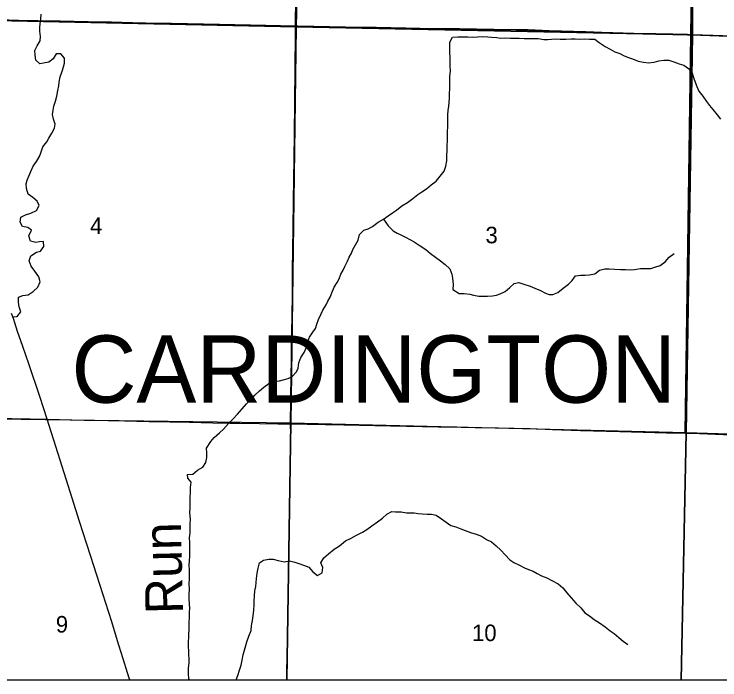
# Model space of a CAD drawing. Extents: x 0 to 34, y 0 to 22.
# Drawn here: x 5.278 to 7.066, y 14 to 15.686 of the extents above; entities that cross this region are included whole.
import ezdxf

# ---------------------------------------------------------------- set-up
doc = ezdxf.new("R2010")
doc.units = 0
for name, color, linetype in [('Default', 7, 'Continuous'), ('GM_X_City_Street', 7, 'Continuous'), ('GM_X_Corporation_Text', 7, 'Continuous'), ('GM_X_Interchange_Ramps', 7, 'Continuous'), ('GM_X_Major_River_Text', 7, 'Continuous'), ('GM_X_Minor_River', 7, 'Continuous'), ('GM_X_Section', 7, 'Continuous'), ('GM_X_Unincorporated_Location', 7, 'Continuous'), ('SH_Cut_Line', 7, 'Continuous'), ('SH_Text', 7, 'Continuous')]:
    doc.layers.add(name, color=color, linetype=linetype)

msp = doc.modelspace()

# ---------------------------------------------------------------- linework, layer by layer
at = {"layer": 'Default'}
for points in [[(7.0145, 17.1525), (7.0025, 16.32), (6.9926, 15.6339), (6.978, 14.6253), (6.9941, 14.625), (7.0745, 14.6221)], [(5.2396, 15.6714), (5.2884, 15.6704), (5.3381, 15.6694), (5.394, 15.6683), (5.4654, 15.6668), (5.5244, 15.6654), (5.5772, 15.6642), (5.6114, 15.6635), (5.6766, 15.6622), (5.7977, 15.6597), (5.9158, 15.6575), (5.9904, 15.6556), (5.9965, 15.6555), (6.1176, 15.6533), (6.1953, 15.6519), (6.2698, 15.6504), (6.3413, 15.6493), (6.4065, 15.6489), (6.4935, 15.6475), (6.5494, 15.6467), (6.5805, 15.646), (6.6332, 15.6442), (6.7264, 15.6417), (6.7668, 15.64), (6.7947, 15.6388), (6.8475, 15.6374), (6.9034, 15.6361), (6.9468, 15.6351), (6.9841, 15.6342), (6.9926, 15.6339), (7.0025, 16.32)], [(7.0745, 14.6221), (6.9941, 14.625), (6.978, 14.6253), (6.9926, 15.6339), (6.9841, 15.6342), (6.9468, 15.6351), (6.9034, 15.6361), (6.8475, 15.6374), (6.7947, 15.6388), (6.7668, 15.64), (6.7264, 15.6417), (6.6332, 15.6442), (6.5805, 15.646), (6.5494, 15.6467), (6.4935, 15.6475), (6.4065, 15.6489), (6.3413, 15.6493), (6.2698, 15.6504), (6.1953, 15.6519), (6.1176, 15.6533), (5.9965, 15.6555), (5.9904, 15.6556), (5.9158, 15.6575), (5.7977, 15.6597), (5.6766, 15.6622), (5.6114, 15.6635), (5.5772, 15.6642), (5.5244, 15.6654), (5.4654, 15.6668), (5.394, 15.6683), (5.3381, 15.6694), (5.2884, 15.6704), (5.2396, 15.6714)], [(2.9377, 14), (7.9275, 14)]]:
    msp.add_lwpolyline(points, dxfattribs=at)
for points in [[(4.9774, 14), (5.9688, 14), (5.9788, 14.6503), (4.9836, 14.6638)], [(5.9688, 14), (6.9678, 14), (6.9808, 14.6254), (5.9788, 14.6503)], [(6.9678, 14), (7.9307, 14), (7.9448, 14.3373), (7.9551, 14.5952), (6.9808, 14.6254)]]:
    msp.add_lwpolyline(points, close=True, dxfattribs=at)
at = {"layer": 'GM_X_City_Street'}
for points in [[(5.9907, 15.6551), (5.9907, 15.6636), (5.9909, 15.6791), (5.9921, 15.7319), (5.9933, 15.7816), (5.9942, 15.822), (5.9965, 15.9277), (5.9973, 15.9649), (5.9979, 15.9991), (5.9988, 16.0551), (6.0006, 16.1545), (6.0016, 16.198), (6.0023, 16.2353), (6.0032, 16.2881), (6.0042, 16.3347), (6.0058, 16.4159)], [(5.2398, 15.6709), (5.2886, 15.6698), (5.3383, 15.6688), (5.3942, 15.6678), (5.4656, 15.6662), (5.5246, 15.6649), (5.5774, 15.6637), (5.6116, 15.663), (5.6768, 15.6617), (5.7979, 15.6591), (5.916, 15.6569), (5.9907, 15.6551)], [(5.9907, 15.6551), (5.9967, 15.6549), (6.1179, 15.6527), (6.1955, 15.6513), (6.2701, 15.6499), (6.3415, 15.6488), (6.3796, 15.6485)], [(6.3796, 15.6485), (6.4067, 15.6484), (6.4937, 15.647), (6.5496, 15.6462), (6.5807, 15.6455), (6.6335, 15.6437), (6.7266, 15.6411), (6.7508, 15.6401)], [(6.7508, 15.6401), (6.767, 15.6395), (6.7949, 15.6382), (6.8477, 15.6369), (6.9036, 15.6356), (6.9471, 15.6345), (6.9843, 15.6336), (6.9928, 15.6334)], [(6.9928, 15.6334), (7.0402, 15.6319), (7.0868, 15.6305), (7.1613, 15.6285), (7.2265, 15.6267), (7.2855, 15.625), (7.3632, 15.6225), (7.4315, 15.6206), (7.4563, 15.6198), (7.4905, 15.6191), (7.4938, 15.619)]]:
    msp.add_lwpolyline(points, dxfattribs=at)
at = {"layer": 'GM_X_Interchange_Ramps'}
for points in [[(5.9783, 14.6481), (5.9783, 14.6505), (5.9788, 14.7096), (5.9797, 14.7749), (5.9801, 14.8059), (5.9809, 14.8588), (5.9819, 14.9147), (5.9829, 14.9831), (5.9834, 15.0422), (5.984, 15.0857), (5.9848, 15.1478), (5.9855, 15.21), (5.9868, 15.2722), (5.9873, 15.3157), (5.988, 15.3872), (5.9889, 15.4556), (5.99, 15.555), (5.9906, 15.6297), (5.9906, 15.6441), (5.9907, 15.6551)], [(5.3613, 14.6602), (5.3425, 14.7179), (5.3148, 14.8004), (5.2997, 14.8445), (5.2865, 14.8827), (5.2759, 14.9151), (5.2714, 14.9283)], [(4.9831, 14.6676), (4.9983, 14.6676), (5.0667, 14.6663), (5.1071, 14.6656), (5.1661, 14.6644), (5.2251, 14.6631), (5.3183, 14.6613), (5.3556, 14.6604), (5.3613, 14.6602)], [(5.5705, 14), (5.5691, 14.0042), (5.5498, 14.0665), (5.5424, 14.0902), (5.525, 14.1466), (5.4871, 14.265), (5.4711, 14.3154), (5.4434, 14.4011), (5.4246, 14.4603), (5.3993, 14.5403), (5.3835, 14.5907), (5.3666, 14.6441), (5.3613, 14.6602)], [(5.3613, 14.6602), (5.455, 14.658), (5.516, 14.6568), (5.5575, 14.6561), (5.6196, 14.6544), (5.6724, 14.6534), (5.7221, 14.6528), (5.7811, 14.6514), (5.8246, 14.6502), (5.8494, 14.6498), (5.8991, 14.6493), (5.9457, 14.6485), (5.9783, 14.6481)], [(5.9686, 14), (5.969, 14.0258), (5.9701, 14.0817), (5.9718, 14.1719), (5.9732, 14.2527), (5.9738, 14.29), (5.9742, 14.3211), (5.9747, 14.3583), (5.976, 14.4392), (5.9771, 14.5169), (5.9777, 14.5666), (5.9784, 14.6226), (5.9783, 14.6481)], [(5.9783, 14.6481), (5.9799, 14.6481), (6.0203, 14.6476), (6.0669, 14.6468), (6.1135, 14.6459), (6.2315, 14.6437), (6.3527, 14.6413), (6.3993, 14.6405), (6.4104, 14.6403)], [(6.4104, 14.6403), (6.4459, 14.6396), (6.5049, 14.6385), (6.5856, 14.6366), (6.6415, 14.6345), (6.7129, 14.632), (6.7782, 14.6303), (6.8123, 14.6292), (6.9304, 14.6261), (6.9782, 14.6247)], [(6.9782, 14.6247), (6.9944, 14.6245), (7.0747, 14.6216), (7.1304, 14.62), (7.2045, 14.6182), (7.2347, 14.6173)]]:
    msp.add_lwpolyline(points, dxfattribs=at)
at = {"layer": 'GM_X_Section'}
for points in [[(5.3517, 15.1102), (5.3419, 15.1095), (5.3324, 15.1079), (5.3195, 15.1109), (5.3153, 15.1249), (5.3216, 15.1386), (5.3121, 15.1461), (5.2985, 15.1484), (5.2931, 15.1594), (5.295, 15.1723), (5.3067, 15.178), (5.3204, 15.1822), (5.334, 15.1887), (5.3411, 15.2016), (5.3362, 15.2126), (5.3248, 15.2217), (5.313, 15.23), (5.3091, 15.2444), (5.3083, 15.2565), (5.311, 15.266), (5.3151, 15.2755), (5.32, 15.288), (5.326, 15.3013), (5.3347, 15.3131), (5.3422, 15.3253), (5.3456, 15.3347), (5.3501, 15.3503), (5.3603, 15.3625), (5.366, 15.372), (5.3735, 15.3849), (5.3799, 15.3974), (5.3818, 15.4073), (5.3775, 15.4198), (5.3745, 15.4323), (5.3763, 15.4426), (5.3786, 15.4528), (5.3827, 15.4657), (5.3861, 15.4786), (5.3883, 15.4927), (5.3909, 15.5044), (5.392, 15.5139), (5.3942, 15.5272), (5.3995, 15.542), (5.4032, 15.5526), (5.4055, 15.5621), (5.4054, 15.5746), (5.3963, 15.5856), (5.3841, 15.5859), (5.3762, 15.5726), (5.3653, 15.5643), (5.3524, 15.5616), (5.3425, 15.5604), (5.333, 15.5695), (5.3307, 15.582), (5.3303, 15.5937), (5.3359, 15.6059), (5.3434, 15.6184), (5.3442, 15.6298), (5.3426, 15.6427), (5.3426, 15.6522), (5.3437, 15.6617), (5.3455, 15.6738), (5.3466, 15.6863)], [(6.0444, 14.9005), (6.0492, 14.9131), (6.0553, 14.9271), (6.0598, 14.9366), (6.0681, 14.9499), (6.0722, 14.9594), (6.0783, 14.9693), (6.0831, 14.9799), (6.0888, 14.9944), (6.0963, 15.0061), (6.1012, 15.016), (6.1054, 15.0274), (6.111, 15.0377), (6.1159, 15.0472), (6.1223, 15.0608), (6.1268, 15.0703), (6.1325, 15.0806), (6.1359, 15.0901), (6.1423, 15.1015), (6.149, 15.114), (6.1524, 15.1281), (6.1638, 15.1391), (6.1744, 15.1422), (6.1861, 15.1483), (6.1997, 15.1589), (6.2137, 15.1666), (6.2258, 15.1753), (6.2364, 15.1826), (6.2463, 15.1894), (6.2603, 15.2009), (6.2743, 15.2093), (6.2879, 15.2192), (6.3007, 15.2294), (6.3106, 15.2359), (6.3223, 15.2435), (6.3348, 15.2535), (6.3469, 15.263), (6.3575, 15.2755), (6.3677, 15.2885), (6.3718, 15.3014), (6.3737, 15.3143), (6.374, 15.3279), (6.3747, 15.3408), (6.3746, 15.3541), (6.3757, 15.364), (6.3757, 15.3768), (6.376, 15.3901), (6.3768, 15.4), (6.3763, 15.4095), (6.3763, 15.422), (6.377, 15.4315), (6.3777, 15.4417), (6.3792, 15.4531), (6.3803, 15.4626), (6.381, 15.4732), (6.381, 15.4846), (6.3813, 15.4975), (6.3817, 15.5073), (6.3813, 15.518), (6.382, 15.5282), (6.3831, 15.5422), (6.3826, 15.554), (6.3822, 15.5665), (6.3826, 15.576), (6.3821, 15.5893), (6.3813, 15.6029), (6.3817, 15.6154), (6.3885, 15.6276), (6.4021, 15.6284), (6.4135, 15.6288), (6.4275, 15.6285), (6.4385, 15.6281), (6.4514, 15.6289), (6.4651, 15.6297), (6.4776, 15.6286), (6.4871, 15.6279), (6.5007, 15.6272), (6.5102, 15.6257), (6.5231, 15.6261), (6.5353, 15.625), (6.5573, 15.6251), (6.5702, 15.6248), (6.5815, 15.6248), (6.5941, 15.6245), (6.6058, 15.6241), (6.6199, 15.6223), (6.6297, 15.6223), (6.6392, 15.6227), (6.6513, 15.6235), (6.6616, 15.6224), (6.676, 15.6228), (6.6893, 15.6233), (6.6991, 15.6233), (6.709, 15.623), (6.7223, 15.6234), (6.7359, 15.6227), (6.7488, 15.6227), (6.7602, 15.614), (6.7754, 15.6038), (6.7876, 15.597), (6.7994, 15.5906)], [(6.7994, 15.5906), (6.8123, 15.5865), (6.8237, 15.5809), (6.834, 15.5763), (6.8442, 15.573), (6.859, 15.5673), (6.8723, 15.5643), (6.8852, 15.5632), (6.8992, 15.5648), (6.911, 15.5679), (6.9243, 15.5694), (6.9364, 15.5695), (6.9493, 15.5653), (6.9626, 15.5605), (6.9748, 15.5567), (6.9866, 15.5484), (6.9957, 15.5363), (6.9999, 15.5234), (7.003, 15.5139), (7.0072, 15.5026), (7.0129, 15.4912), (7.0225, 15.4784), (7.032, 15.4651), (7.04, 15.4549), (7.048, 15.4443), (7.0594, 15.4307), (7.0678, 15.4201)], [(6.2137, 15.1666), (6.2255, 15.1499), (6.2385, 15.1375), (6.248, 15.1314), (6.2579, 15.1273), (6.2693, 15.1216), (6.2822, 15.1148), (6.2917, 15.1092), (6.3065, 15.099), (6.3206, 15.0899), (6.3331, 15.0801), (6.3453, 15.0707), (6.3579, 15.0616), (6.37, 15.0522), (6.3818, 15.0408), (6.3864, 15.0276), (6.3884, 15.0174), (6.3899, 15.0018), (6.3896, 14.9889), (6.4056, 14.9787), (6.4177, 14.9788), (6.4321, 14.9773), (6.4416, 14.9747), (6.4549, 14.9721), (6.4678, 14.9717), (6.4773, 14.9721), (6.4898, 14.9726), (6.5, 14.9745), (6.5095, 14.9776), (6.5216, 14.984), (6.5337, 14.9936), (6.5447, 15.0038), (6.5564, 15.0062), (6.5694, 15.002), (6.5849, 14.9975), (6.5967, 14.9923), (6.6111, 14.9859), (6.6241, 14.9798), (6.6336, 14.9764), (6.643, 14.9761), (6.6555, 14.9811), (6.6692, 14.9921), (6.682, 15.002), (6.6915, 15.0119), (6.7001, 15.0233), (6.7138, 15.0253), (6.7248, 15.0253), (6.7347, 15.0261), (6.7487, 15.0288), (6.7608, 15.0375), (6.7748, 15.0414), (6.7851, 15.0414), (6.7995, 15.0403), (6.8139, 15.0396), (6.8264, 15.0393), (6.8401, 15.0389), (6.8499, 15.0397), (6.8651, 15.0417), (6.8913, 15.0418), (6.9015, 15.0452), (6.9144, 15.0494), (6.9269, 15.059), (6.9378, 15.0704), (6.9499, 15.0803)], [(5.2762, 14.9196), (5.2856, 14.92), (5.2947, 14.9318), (5.2901, 14.9447), (5.2885, 14.9568), (5.2885, 14.9693), (5.2999, 14.9739), (5.3131, 14.9755), (5.3256, 14.9835), (5.3377, 14.9945), (5.3434, 15.0078), (5.3403, 15.0211), (5.33, 15.0351), (5.3208, 15.0476), (5.3162, 15.0612), (5.32, 15.0741), (5.3344, 15.0836), (5.3442, 15.0859), (5.3529, 15.0974), (5.3517, 15.1102)], [(5.7224, 14), (5.7206, 14.003), (5.7198, 14.0162), (5.7197, 14.0295), (5.7208, 14.0435), (5.7215, 14.053), (5.7203, 14.0632), (5.7203, 14.0739), (5.7199, 14.0841), (5.7195, 14.0974), (5.7202, 14.1072), (5.7202, 14.1167), (5.7209, 14.1262), (5.7216, 14.1361), (5.7216, 14.1467), (5.7223, 14.1573), (5.7222, 14.171), (5.7226, 14.1823), (5.7222, 14.1918), (5.7214, 14.2062), (5.7209, 14.2176), (5.722, 14.2286), (5.7216, 14.2445), (5.7219, 14.2555), (5.7219, 14.2779), (5.7214, 14.2912), (5.7218, 14.3007), (5.7233, 14.3143), (5.7232, 14.3238), (5.7228, 14.3367), (5.7228, 14.3477), (5.7223, 14.3598), (5.7234, 14.3727), (5.7234, 14.3837), (5.7237, 14.3951), (5.7244, 14.4069), (5.7233, 14.4228), (5.7236, 14.4357), (5.7235, 14.4489), (5.7239, 14.4618), (5.7242, 14.4751), (5.7245, 14.4869), (5.726, 14.5005), (5.7176, 14.5107), (5.7172, 14.5202), (5.7301, 14.5206), (5.7426, 14.5309), (5.7558, 14.5385), (5.7638, 14.5503), (5.7656, 14.5632), (5.766, 14.5754), (5.7652, 14.5867), (5.7757, 14.6035), (5.7848, 14.6141), (5.7984, 14.6259), (5.8082, 14.6354), (5.8207, 14.6491), (5.8317, 14.6602), (5.8437, 14.6727), (5.8558, 14.6868), (5.8668, 14.699), (5.8766, 14.7081), (5.888, 14.721), (5.8993, 14.7321), (5.9106, 14.7412), (5.9231, 14.7503), (5.9371, 14.7557), (5.9497, 14.7576), (5.9595, 14.7603), (5.972, 14.7634), (5.9822, 14.768), (5.9932, 14.7798), (5.9973, 14.7893), (5.9992, 14.8029), (6.0041, 14.8162), (6.0128, 14.8291), (6.0184, 14.8424), (6.0214, 14.8557), (6.0263, 14.8682), (6.0346, 14.8808), (6.0414, 14.8903), (6.0444, 14.9005)], [(5.8403, 14), (5.8404, 14.0003), (5.8442, 14.0109), (5.8491, 14.025), (5.8528, 14.0375), (5.8551, 14.0497), (5.8584, 14.0633), (5.861, 14.0755), (5.8644, 14.0869), (5.8674, 14.0964), (5.8723, 14.1108), (5.8779, 14.1248), (5.879, 14.1377), (5.882, 14.1506), (5.8831, 14.1624), (5.885, 14.1764), (5.886, 14.1901), (5.886, 14.1996), (5.8871, 14.2132), (5.8878, 14.2257), (5.89, 14.2367), (5.8911, 14.247), (5.8919, 14.2568), (5.8933, 14.2701), (5.8963, 14.283), (5.8997, 14.2967), (5.9095, 14.3032), (5.9232, 14.3059), (5.9342, 14.3055), (5.9471, 14.3025), (5.9615, 14.2992), (5.9752, 14.3011), (5.9888, 14.2981), (6.0014, 14.2936), (6.0112, 14.2906), (6.0242, 14.2857), (6.0348, 14.274), (6.0466, 14.2646), (6.058, 14.2714), (6.0598, 14.2847), (6.0548, 14.2968), (6.0624, 14.3094), (6.0741, 14.3196), (6.0885, 14.3311), (6.1017, 14.3398), (6.1172, 14.352), (6.1316, 14.3593), (6.1456, 14.3665), (6.1604, 14.3742), (6.1714, 14.381), (6.1839, 14.3898), (6.1982, 14.4001), (6.2107, 14.4092), (6.2221, 14.4195), (6.2346, 14.4267), (6.2444, 14.426), (6.2581, 14.4257), (6.2717, 14.4231), (6.2816, 14.4231), (6.2915, 14.4228), (6.3013, 14.4217), (6.312, 14.4206), (6.3245, 14.4198), (6.3355, 14.4199), (6.3473, 14.4169), (6.3602, 14.4078), (6.3727, 14.3995), (6.3845, 14.3912), (6.397, 14.3875), (6.4092, 14.3826), (6.4206, 14.3784), (6.4339, 14.3735), (6.4483, 14.3694), (6.4616, 14.3642), (6.4749, 14.3555), (6.4871, 14.3498), (6.4993, 14.3396), (6.5107, 14.3283), (6.5217, 14.3166), (6.5339, 14.3037), (6.5438, 14.2977), (6.5578, 14.2905), (6.5708, 14.2837), (6.5806, 14.2792), (6.5932, 14.2755), (6.6027, 14.2698), (6.6137, 14.2638), (6.6274, 14.2581), (6.6399, 14.2521), (6.6559, 14.2431), (6.6677, 14.2329), (6.6779, 14.2208), (6.6894, 14.2079)], [(6.6894, 14.2079), (6.7012, 14.1947), (6.7134, 14.1822), (6.724, 14.1701), (6.7354, 14.1618), (6.7476, 14.1527), (6.7609, 14.1441), (6.775, 14.1342), (6.7883, 14.1244), (6.7978, 14.1172), (6.8096, 14.107), (6.821, 14.098), (6.8324, 14.0897)]]:
    msp.add_lwpolyline(points, dxfattribs=at)
at = {"layer": 'GM_X_Unincorporated_Location'}
for points in [[(6.0154, 16.6684), (5.9927, 15.6543), (4.9903, 15.675), (5.0069, 16.682)], [(7.0019, 16.6421), (6.9963, 15.6339), (5.9927, 15.6543), (6.0154, 16.6684)], [(8.0033, 16.6164), (7.9948, 16.3527), (7.9737, 15.6015), (6.9963, 15.6339), (7.0019, 16.6421)], [(5.9927, 15.6543), (5.9788, 14.6503), (4.9836, 14.6638), (4.9903, 15.675)], [(6.9963, 15.6339), (6.9808, 14.6254), (5.9788, 14.6503), (5.9927, 15.6543)], [(6.9963, 15.6339), (7.9737, 15.6015), (7.9679, 15.3374), (7.9551, 14.5952), (6.9808, 14.6254)]]:
    msp.add_lwpolyline(points, close=True, dxfattribs=at)
at = {"layer": 'SH_Cut_Line'}
msp.add_line((2, 14), (9, 14), dxfattribs=at)
at = {"layer": 'SH_Text'}
msp.add_lwpolyline([(2.9377, 14), (8.8, 14), (8.8, 20.8), (2.9842, 20.8), (2.984, 20.7397), (2.9904, 20.3395), (2.9796, 19.7242), (2.9753, 18.7199), (2.9708, 17.6769), (2.9623, 15.7101), (2.9479, 14.7065)], close=True, dxfattribs=at)

# ---------------------------------------------------------------- texts
at = {"layer": 'GM_X_Corporation_Text'}
msp.add_text('CARDINGTON', height=0.17045, rotation=0, dxfattribs=at).set_placement((5.4229, 14.702))
at = {"layer": 'GM_X_Major_River_Text'}
for s, height, p in [('4', 0.0419, (5.47, 15.1293)), ('3', 0.0419, (6.472, 15.1057)), ('9', 0.0419, (5.3833, 14.1199)), ('10', 0.04186, (6.4379, 14.0982))]:
    msp.add_text(s, height=height, rotation=0, dxfattribs=at).set_placement(p)
at = {"layer": 'GM_X_Minor_River'}
msp.add_text('Run', height=0.09471, rotation=91.3563, dxfattribs=at).set_placement((5.7057, 14.1677))

doc.saveas('drawing.dxf')
